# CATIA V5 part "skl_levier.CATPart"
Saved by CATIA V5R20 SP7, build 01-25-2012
Part number: skl_levier
Publications: "Plan.1", "Axe_pivot_levier_bâti", "Axe_pivot_levier_bielette_droite", "Axe_pivot_levier_biellette_gauche"
Bounding box of the stored display mesh (mm): x -68.75 to 200, y 627.38 to 772.62, z 0 to 20
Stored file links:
  U:\IAO\thinkmotion catia2\skl_levier.CATPart
  U:\IAO\thinkmotion catia2\skl_862_adubourgno.CATProduct
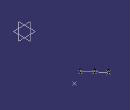
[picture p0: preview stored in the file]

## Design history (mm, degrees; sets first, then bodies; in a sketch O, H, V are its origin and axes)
Set1
  Point1 "A": linked copy from another document
  Point2 "B": linked copy from another document
  Point3 "B2": linked copy from another document
  Plane1: linked copy from another document
  Point4 "F": linked copy from another document
Set2
  Line1: type PtPt, FirstPoint Point1, SecondPoint Point2
  Line2: type PtPt, FirstPoint Point1, SecondPoint Point3
  Line3 "Axe_pivot_levier_bâti": type Normal, RefPoint Point1, RefSkin Plane1, Start 0, End 20
  Line4 "Axe_pivot_levier_bielette_droite": type Normal, RefPoint Point2, RefSkin Plane1, Start 0, End 20
  Line5 "Axe_pivot_levier_biellette_gauche": type Normal, RefPoint Point3, RefSkin Plane1, Start 0, End 20
Body1 (main body)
